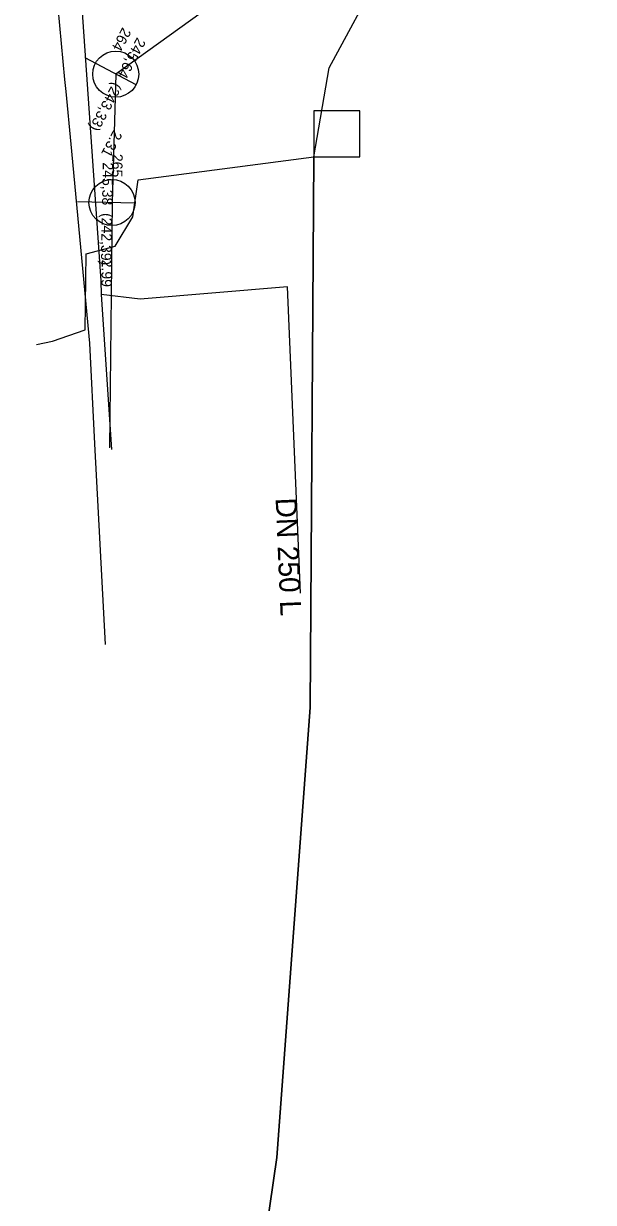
# Model space of a CAD drawing. Extents: x -600636 to -600148, y -1203980 to -1203569.
# Drawn here: x -600603.9 to -600579.1, y -1203856 to -1203804.8 of the extents above; entities that cross this region are included whole.
import ezdxf

# ---------------------------------------------------------------- set-up
doc = ezdxf.new("R2010")
doc.units = 0
for name, color, linetype in [('Cetin kolektor kabelovod', 7, 'Continuous'), ('Cetin nezaměřený', 7, 'Continuous'), ('Cetin zam průběh', 7, 'Continuous'), ('GasNet NTL', 7, 'Continuous'), ('Implicitní', 7, 'Continuous'), ('VaK Břeclav_kanalizace', 7, 'Continuous'), ('Vak Břeclav_vodovod', 7, 'Continuous')]:
    doc.layers.add(name, color=color, linetype=linetype)

# ---------------------------------------------------------------- blocks, each defined once
blk = doc.blocks.new('MoSymbol 2')
at = {"layer": 'Implicitní'}
blk.add_line((0, 0.0005), (0, -0.00075), dxfattribs=at)
blk.add_circle((0, 0), 0.0005, dxfattribs=at)

msp = doc.modelspace()

# ---------------------------------------------------------------- linework, layer by layer
at = {"layer": 'Cetin kolektor kabelovod'}
msp.add_lwpolyline([(-600591.27, -1203810.59), (-600589.27, -1203810.59), (-600589.27, -1203808.59), (-600591.27, -1203808.59)], close=True, dxfattribs=at)
msp.add_lwpolyline([(-600591.27, -1203810.59), (-600591.42, -1203834.51), (-600592.87, -1203854.05), (-600594.24, -1203863.54), (-600596.19, -1203870.6), (-600600.04, -1203881.6), (-600600.23, -1203882.56), (-600600.33, -1203883.34), (-600600.16, -1203883.94), (-600599.08, -1203885.54), (-600598.54, -1203885.98)], dxfattribs=at)
at = {"layer": 'Cetin nezaměřený'}
msp.add_lwpolyline([(-600600.33, -1203883.34), (-600600.23, -1203882.56), (-600600.04, -1203881.6), (-600596.19, -1203870.6), (-600594.24, -1203863.54), (-600592.87, -1203854.05), (-600591.42, -1203834.51), (-600591.27, -1203810.59)], dxfattribs=at)
at = {"layer": 'Cetin zam průběh'}
for points in [[(-600591.27, -1203810.59), (-600590.6, -1203806.73), (-600588.32, -1203802.51), (-600586.01, -1203800.08), (-600583.97, -1203798.69), (-600581.13, -1203796.91), (-600575.98, -1203796.07), (-600574.075, -1203796.372)], [(-600603.31, -1203818.74), (-600602.61, -1203818.6), (-600601.2, -1203818.11), (-600601.15, -1203814.8), (-600599.89, -1203814.47), (-600599.12, -1203813.2), (-600598.9, -1203811.59), (-600591.27, -1203810.59)]]:
    msp.add_lwpolyline(points, dxfattribs=at)
at = {"layer": 'GasNet NTL'}
msp.add_lwpolyline([(-600589.51, -1203786.96), (-600603.87, -1203790.9), (-600603.51, -1203792.65), (-600602.6, -1203801.75), (-600602.09, -1203807.23), (-600602.04, -1203807.76), (-600601.82, -1203810.05), (-600601.01, -1203818.68), (-600600.79, -1203823.05), (-600600.33, -1203831.768)], dxfattribs=at)
at = {"layer": 'VaK Břeclav_kanalizace'}
for p, q in [((-600583.255, -1203795.061), (-600599.868, -1203807.001)), ((-600599.868, -1203807.001), (-600600.029, -1203812.578)), ((-600600.029, -1203812.578), (-600600.143, -1203823.226))]:
    msp.add_line(p, q, dxfattribs=at)
at = {"layer": 'Vak Břeclav_vodovod'}
msp.add_line((-600600.505, -1203816.572), (-600600.052, -1203823.295), dxfattribs=at)
for points in [[(-600601.355, -1203803.909), (-600600.518, -1203815.976), (-600600.505, -1203816.572)], [(-600591.84, -1203829.536), (-600592.406, -1203816.237), (-600598.806, -1203816.771), (-600600.505, -1203816.572)]]:
    msp.add_lwpolyline(points, dxfattribs=at)

# ---------------------------------------------------------------- block references
at = {"layer": 'VaK Břeclav_kanalizace'}
for p, xscale, yscale, rotation in [((-600599.868, -1203807.001), 1999.750031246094, 1999.7500312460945, -117.97412332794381), ((-600600.029, -1203812.578), 1999.7500312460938, 1999.750031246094, -91.13240440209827)]:
    msp.add_blockref('MoSymbol 2', p, dxfattribs=dict(at, xscale=xscale, yscale=yscale, rotation=rotation))

# ---------------------------------------------------------------- texts
for s, height, rotation, p in [('245,64  (243,33)', 0.45494, 242.0259, (-600598.939, -1203805.381)), ('264', 0.4549, 242.0259, (-600599.573, -1203804.946)), ('2.31', 0.4549, 242.0259, (-600599.96, -1203809.404)), ('265', 0.4549, 268.8676, (-600600.017, -1203810.461)), ('245,38  (242,39)', 0.45494, 268.8676, (-600600.428, -1203810.832)), ('2.99', 0.4549, 268.8676, (-600600.47, -1203815.054))]:
    msp.add_text(s, height=height, rotation=rotation, dxfattribs=at).set_placement(p)
at = {"layer": 'Vak Břeclav_vodovod'}
msp.add_text('DN 250 L', height=0.9099, rotation=272.4385, dxfattribs=at).set_placement((-600592.926, -1203825.412))

doc.saveas('drawing.dxf')
